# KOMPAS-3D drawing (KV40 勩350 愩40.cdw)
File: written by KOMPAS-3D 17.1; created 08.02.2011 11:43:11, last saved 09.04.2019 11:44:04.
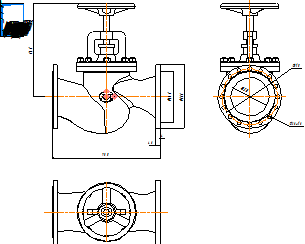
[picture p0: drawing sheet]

Sheet 1: A4, portrait

Title block, sheet 1: name: KV 40 Ду350; material: Внимание! Данный продукт является объектом авторского права ООО «Торговый Дом АДЛ». / Запрещается изменение, копирование, распространение / (в том числе путем копирования на другие сайты и ресурсы в Интернете) / или любое иное использование информации и объектов без предварительного / согласия правообладателя (ООО «Торговый Дом АДЛ»).; scale: 1:1; sheets: 1; organisation: ООО "Торговый дом АДЛ"; sheet format: A4; stored path: \\adlc.lan\data\АДЛ_ПКД\3D-модели\ADL production\Вентили ГРАНВЕНТ\KV40\KOMPAS 2D\KV 40 Ду350.cdw

Views: Спереди 1, Проекционный вид 2, Проекционный вид 3
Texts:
  Viktor2
Dimensions and other numbers on the sheet: 465; 580; 980; 845; 510; 36; 350; 46; 4; 1:1; 1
